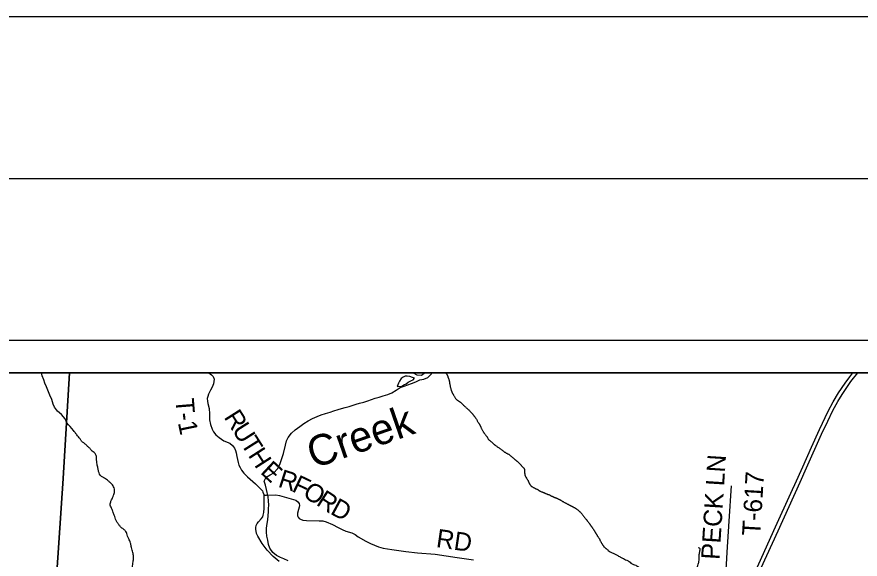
# Model space of a CAD drawing. Extents: x -13.7 to 34, y 0 to 32.3.
# Drawn here: x 25.84 to 28.447, y 20.324 to 22 of the extents above; entities that cross this region are included whole.
import ezdxf

# ---------------------------------------------------------------- set-up
doc = ezdxf.new("R2010")
doc.units = 0
for name, color, linetype in [('GM_X_Corporation', 7, 'Continuous'), ('GM_X_Major_River', 7, 'Continuous'), ('GM_X_Major_River_Text', 7, 'Continuous'), ('GM_X_Minor_River', 7, 'Continuous'), ('GM_X_State_Route', 7, 'Continuous'), ('GM_X_Township_Road', 7, 'Continuous'), ('GM_X_Township_Road_Text', 7, 'Continuous'), ('SH_Border', 7, 'Continuous'), ('SH_Cut_Line', 7, 'Continuous'), ('SH_Data', 7, 'Continuous')]:
    doc.layers.add(name, color=color, linetype=linetype)

msp = doc.modelspace()

# ---------------------------------------------------------------- linework, layer by layer
at = {"layer": 'GM_X_Corporation'}
for points in [[(25.8396, 18.3951), (25.8512, 18.5523), (25.8521, 18.5644), (25.8715, 18.8281), (25.8969, 19.1723), (25.8969, 19.2407), (25.917, 19.5276), (25.9325, 19.8164), (25.9462, 20.0191), (25.9566, 20.1753), (25.9834, 20.5724), (26.0026, 20.9), (23.5167, 20.9)], [(25.8396, 18.3951), (25.8512, 18.5523), (25.8521, 18.5644), (25.8715, 18.8281), (25.8969, 19.1723), (25.8969, 19.2407), (25.917, 19.5276), (25.9325, 19.8164), (25.9462, 20.0191), (25.9566, 20.1753), (25.9834, 20.5724), (26.0026, 20.9), (23.5167, 20.9)], [(29.9598, 20.9), (26.0026, 20.9), (25.9834, 20.5724), (25.9566, 20.1753), (25.9462, 20.0191), (25.9325, 19.8164), (25.917, 19.5276), (25.8969, 19.2407), (25.8969, 19.1723), (25.8715, 18.8281), (25.8521, 18.5644), (25.8512, 18.5523), (25.8396, 18.3951), (25.8286, 18.2247), (25.8036, 17.8534), (25.7648, 17.1991), (25.7595, 17.1252), (25.7591, 17.1039), (25.7561, 17.0683), (25.752, 17.037), (25.7481, 16.9763), (25.7164, 16.6052), (25.6857, 16.1459), (25.6733, 15.948)], [(29.9598, 20.9), (26.0026, 20.9), (25.9834, 20.5724), (25.9566, 20.1753), (25.9462, 20.0191), (25.9325, 19.8164), (25.917, 19.5276), (25.8969, 19.2407), (25.8969, 19.1723), (25.8715, 18.8281), (25.8521, 18.5644), (25.8512, 18.5523), (25.8396, 18.3951), (25.8286, 18.2247), (25.8036, 17.8534), (25.7648, 17.1991), (25.7595, 17.1252), (25.7591, 17.1039), (25.7561, 17.0683), (25.752, 17.037), (25.7481, 16.9763), (25.7164, 16.6052), (25.6857, 16.1459), (25.6733, 15.948)]]:
    msp.add_lwpolyline(points, dxfattribs=at)
at = {"layer": 'GM_X_Major_River'}
for points in [[(26.6785, 20.3183), (26.6649, 20.3243), (26.6554, 20.3285), (26.6429, 20.3353), (26.6312, 20.3443), (26.6224, 20.3576), (26.6179, 20.3693), (26.6159, 20.3822), (26.6129, 20.3943), (26.6117, 20.4072), (26.6121, 20.419), (26.6139, 20.4341), (26.6154, 20.4451), (26.6173, 20.4584), (26.6176, 20.4698), (26.6184, 20.4804), (26.6187, 20.4906), (26.6179, 20.5035), (26.6168, 20.5164), (26.6122, 20.5391), (26.6087, 20.552), (26.6049, 20.5645), (26.611, 20.5771), (26.6231, 20.5839), (26.6348, 20.5908), (26.6457, 20.6029), (26.6525, 20.6158), (26.6559, 20.6253), (26.66, 20.6382), (26.6638, 20.65), (26.6702, 20.6758), (26.6736, 20.6891), (26.6792, 20.7001), (26.6886, 20.7126), (26.7007, 20.7237), (26.7143, 20.7335), (26.7276, 20.7431), (26.7408, 20.7507), (26.7544, 20.7579), (26.7684, 20.7644), (26.7809, 20.7701), (26.7937, 20.774), (26.8081, 20.7782), (26.8195, 20.7824), (26.8331, 20.7866), (26.8433, 20.7893), (26.8547, 20.7927), (26.8668, 20.7954), (26.8766, 20.7981), (26.8887, 20.8027), (26.8997, 20.8053), (26.9122, 20.8092), (26.9246, 20.8126), (26.9367, 20.8168), (26.9481, 20.821), (26.9602, 20.8245), (26.9727, 20.8287), (26.9871, 20.8329), (26.9988, 20.8382), (27.0124, 20.8459), (27.0245, 20.8539), (27.037, 20.8588), (27.0491, 20.8623), (27.0604, 20.8661), (27.0733, 20.8714), (27.0858, 20.8775), (27.0979, 20.8798), (27.1107, 20.8848), (27.1213, 20.8962), (27.1228, 20.9)], [(27.0695, 20.8828), (27.0627, 20.8851), (27.0543, 20.8877), (27.0467, 20.8896), (27.0407, 20.8892), (27.0343, 20.8865), (27.0278, 20.8815), (27.0229, 20.8739), (27.0199, 20.8679), (27.0154, 20.8576)], [(27.0154, 20.8576), (27.0298, 20.8588), (27.0366, 20.8622), (27.0434, 20.866), (27.0498, 20.871), (27.0559, 20.8737), (27.0604, 20.8759), (27.0653, 20.8782), (27.0695, 20.8828)], [(27.1019, 20.9), (27.091, 20.8916), (27.0774, 20.8919), (27.066, 20.898), (27.0588, 20.9)]]:
    msp.add_lwpolyline(points, dxfattribs=at)
at = {"layer": 'GM_X_Minor_River'}
msp.add_lwpolyline([(25.9945, 20.7448), (25.9889, 20.7569), (25.9779, 20.7705), (25.9662, 20.7815), (25.9563, 20.7936), (25.9525, 20.8031), (25.9483, 20.8171), (25.9418, 20.8308), (25.9354, 20.8455), (25.9312, 20.8562), (25.927, 20.8679), (25.9232, 20.8781), (25.9187, 20.8906), (25.9159, 20.9)], dxfattribs=at)
msp.add_open_spline([(27.1659, 20.9), (27.166, 20.8999), (27.166, 20.8998), (27.1661, 20.8998), (27.1675, 20.8977), (27.1691, 20.8958), (27.1701, 20.8935), (27.171, 20.8913), (27.1717, 20.8889), (27.1725, 20.8866), (27.1734, 20.8841), (27.1744, 20.8815), (27.1753, 20.8789), (27.1761, 20.8766), (27.1768, 20.8741), (27.1773, 20.8716), (27.1778, 20.8694), (27.1778, 20.867), (27.1782, 20.8648), (27.179, 20.8607), (27.1799, 20.8566), (27.1809, 20.8525), (27.1815, 20.85), (27.182, 20.8474), (27.1829, 20.8449), (27.1837, 20.8424), (27.1848, 20.8402), (27.1861, 20.8379), (27.1871, 20.836), (27.1882, 20.8341), (27.1893, 20.8321), (27.191, 20.8291), (27.1926, 20.8262), (27.1943, 20.8232), (27.1958, 20.8206), (27.1977, 20.818), (27.2002, 20.8162), (27.2022, 20.8147), (27.2044, 20.8133), (27.2065, 20.8118), (27.2083, 20.8105), (27.2102, 20.8092), (27.212, 20.8078), (27.2144, 20.806), (27.2161, 20.8035), (27.2183, 20.8015), (27.2201, 20.7999), (27.222, 20.7984), (27.2238, 20.7968), (27.2265, 20.7943), (27.2292, 20.7918), (27.2319, 20.7893), (27.2339, 20.7875), (27.2358, 20.7856), (27.2378, 20.7838), (27.2402, 20.7815), (27.2425, 20.7791), (27.2448, 20.7767), (27.2466, 20.7748), (27.2483, 20.7729), (27.2499, 20.7708), (27.2515, 20.7688), (27.2531, 20.7667), (27.2546, 20.7646), (27.2562, 20.7623), (27.2579, 20.76), (27.2593, 20.7576), (27.2614, 20.7543), (27.2634, 20.7509), (27.2654, 20.7475), (27.2669, 20.7452), (27.2683, 20.7429), (27.2698, 20.7406), (27.2709, 20.7387), (27.272, 20.7367), (27.273, 20.7347), (27.2742, 20.7324), (27.275, 20.7298), (27.2762, 20.7274), (27.2777, 20.7244), (27.2794, 20.7214), (27.2812, 20.7185), (27.2826, 20.7163), (27.284, 20.7141), (27.2855, 20.7119), (27.2876, 20.709), (27.29, 20.7063), (27.2921, 20.7033), (27.2935, 20.7014), (27.2943, 20.6991), (27.2957, 20.6971), (27.2973, 20.6949), (27.2991, 20.6927), (27.3012, 20.6909), (27.3034, 20.6889), (27.3056, 20.6869), (27.3078, 20.685), (27.3099, 20.6831), (27.312, 20.6813), (27.3141, 20.6794), (27.3158, 20.6779), (27.3177, 20.6765), (27.3196, 20.6751), (27.3233, 20.6723), (27.327, 20.6697), (27.3307, 20.6671), (27.3334, 20.6653), (27.3363, 20.6637), (27.3389, 20.6619), (27.3417, 20.66), (27.344, 20.6575), (27.3467, 20.6556), (27.3491, 20.6538), (27.3516, 20.6523), (27.3541, 20.6508), (27.3566, 20.6492), (27.3596, 20.6485), (27.3619, 20.6467), (27.3642, 20.6449), (27.3664, 20.6431), (27.3686, 20.6412), (27.3712, 20.6389), (27.3738, 20.6367), (27.3763, 20.6344), (27.3783, 20.6327), (27.3803, 20.631), (27.3822, 20.6293), (27.3842, 20.6276), (27.3866, 20.6263), (27.3885, 20.6245), (27.391, 20.6223), (27.3932, 20.6199), (27.3955, 20.6175), (27.3975, 20.6154), (27.3994, 20.6133), (27.4014, 20.6112), (27.4032, 20.6093), (27.4048, 20.6074), (27.4065, 20.6053), (27.408, 20.6036), (27.4091, 20.6014), (27.4093, 20.5992), (27.4096, 20.5969), (27.4093, 20.5946), (27.4095, 20.5923), (27.4096, 20.5904), (27.4097, 20.5885), (27.4101, 20.5866), (27.4112, 20.5813), (27.4138, 20.5766), (27.4164, 20.572), (27.4177, 20.5696), (27.4194, 20.5674), (27.4207, 20.565), (27.4218, 20.563), (27.4225, 20.5608), (27.4236, 20.5588), (27.4247, 20.5566), (27.426, 20.5546), (27.4275, 20.5526), (27.4292, 20.5504), (27.4311, 20.5485), (27.4334, 20.5471), (27.4364, 20.5453), (27.4393, 20.5438), (27.4424, 20.5422), (27.4446, 20.5411), (27.4469, 20.5401), (27.4491, 20.539), (27.4513, 20.5378), (27.4532, 20.5361), (27.4554, 20.535), (27.4586, 20.5333), (27.4618, 20.5318), (27.4651, 20.5305), (27.467, 20.5297), (27.4689, 20.5291), (27.4708, 20.5284), (27.4732, 20.5274), (27.4755, 20.5261), (27.4779, 20.5251), (27.4803, 20.5241), (27.483, 20.5237), (27.4854, 20.5226), (27.4881, 20.5214), (27.4905, 20.5197), (27.4932, 20.5185), (27.4953, 20.5175), (27.4974, 20.5165), (27.4996, 20.5156), (27.5019, 20.5146), (27.5043, 20.5137), (27.5067, 20.5127), (27.5092, 20.5117), (27.5117, 20.5106), (27.5142, 20.5095), (27.5167, 20.5082), (27.5192, 20.5068), (27.5216, 20.5054), (27.5244, 20.5038), (27.527, 20.5021), (27.5298, 20.5006), (27.5325, 20.4991), (27.5353, 20.4976), (27.538, 20.4961), (27.5409, 20.4946), (27.5437, 20.4931), (27.5466, 20.4917), (27.5487, 20.4906), (27.5508, 20.4895), (27.5529, 20.4884), (27.5548, 20.4875), (27.5567, 20.4865), (27.5585, 20.4856), (27.561, 20.4843), (27.5633, 20.4829), (27.5656, 20.4815), (27.5675, 20.4804), (27.5694, 20.4793), (27.5712, 20.4779), (27.5737, 20.4761), (27.5759, 20.474), (27.5782, 20.472), (27.5802, 20.4702), (27.5823, 20.4685), (27.5841, 20.4665), (27.5876, 20.4626), (27.5903, 20.4581), (27.5936, 20.454), (27.5958, 20.4512), (27.5983, 20.4486), (27.6005, 20.4458), (27.6021, 20.4438), (27.6033, 20.4416), (27.6049, 20.4396), (27.6067, 20.4372), (27.6089, 20.435), (27.6107, 20.4326), (27.6121, 20.4307), (27.6133, 20.4286), (27.6147, 20.4267), (27.6161, 20.4248), (27.6177, 20.4229), (27.619, 20.4209), (27.6208, 20.4183), (27.6224, 20.4157), (27.6241, 20.4131), (27.6253, 20.4112), (27.6265, 20.4093), (27.6277, 20.4073), (27.629, 20.4052), (27.63, 20.4029), (27.6313, 20.4007), (27.6327, 20.3984), (27.6341, 20.3961), (27.6356, 20.3937), (27.6372, 20.3912), (27.6391, 20.3889), (27.6407, 20.3864), (27.6418, 20.3844), (27.6424, 20.3822), (27.6435, 20.3802), (27.645, 20.3775), (27.6466, 20.3748), (27.6482, 20.3721), (27.6495, 20.3698), (27.6507, 20.3676), (27.6521, 20.3655), (27.6537, 20.3631), (27.6558, 20.3611), (27.658, 20.3592), (27.6599, 20.3576), (27.662, 20.3561), (27.6639, 20.3544), (27.6662, 20.3523), (27.6686, 20.3502), (27.6709, 20.3481)], degree=3, dxfattribs=at)
for points in [[(26.1039, 20.5779), (26.0976, 20.5834), (26.0941, 20.5903), (26.0917, 20.5995), (26.0904, 20.6053), (26.0895, 20.6114), (26.0881, 20.6175), (26.0869, 20.6252), (26.0861, 20.6354), (26.0845, 20.6465), (26.0787, 20.6532), (26.0724, 20.6575), (26.0669, 20.6646), (26.0607, 20.6705), (26.0533, 20.6776), (26.0467, 20.6831), (26.0404, 20.6882), (26.0353, 20.6956), (26.0306, 20.7015), (26.0255, 20.7077), (26.02, 20.7151), (26.0153, 20.7214), (25.9945, 20.7448)], [(26.2658, 19.8603), (26.2679, 19.867), (26.2699, 19.8727), (26.2728, 19.8786), (26.2745, 19.885), (26.2766, 19.8907), (26.2779, 19.8967), (26.2797, 19.9039), (26.2823, 19.9121), (26.2833, 19.9197), (26.2843, 19.9265), (26.2844, 19.9322), (26.2844, 19.9409), (26.2835, 19.9508), (26.283, 19.9573), (26.2821, 19.9638), (26.2808, 19.9711), (26.2799, 19.9791), (26.2784, 19.9897), (26.2779, 19.9981), (26.2764, 20.021), (26.2755, 20.0282), (26.2745, 20.0343), (26.2732, 20.0408), (26.2701, 20.05), (26.2677, 20.057), (26.2646, 20.065), (26.2615, 20.0746), (26.2598, 20.0823), (26.2589, 20.0899), (26.2578, 20.1013), (26.257, 20.1105), (26.2564, 20.1173), (26.2551, 20.1238), (26.2516, 20.1319), (26.2458, 20.1409), (26.2397, 20.1506), (26.2353, 20.1564), (26.2329, 20.1637), (26.2316, 20.1695), (26.2299, 20.1752), (26.2278, 20.1817), (26.2246, 20.1883), (26.2203, 20.1964), (26.216, 20.2023), (26.2098, 20.2097), (26.2037, 20.2228), (26.2002, 20.2294), (26.1947, 20.236), (26.1915, 20.2433), (26.1902, 20.251), (26.1917, 20.2597), (26.1931, 20.2672), (26.1949, 20.2759), (26.1958, 20.2819), (26.1964, 20.2884), (26.1975, 20.2986), (26.1982, 20.3069), (26.1996, 20.3156), (26.2002, 20.3213), (26.2008, 20.3281), (26.2006, 20.335), (26.1993, 20.3411), (26.1976, 20.348), (26.1956, 20.3556), (26.1936, 20.3629), (26.1913, 20.3729), (26.1888, 20.3802), (26.186, 20.3863), (26.1821, 20.3941), (26.1797, 20.4025), (26.1769, 20.4091), (26.1695, 20.4161), (26.1607, 20.4233), (26.1548, 20.4307), (26.149, 20.4389), (26.1455, 20.4469), (26.1427, 20.4554), (26.1389, 20.4646), (26.1372, 20.4715), (26.1347, 20.4773), (26.1312, 20.4843), (26.1287, 20.4908), (26.1294, 20.498), (26.1327, 20.5066), (26.1359, 20.513), (26.1392, 20.5209), (26.1409, 20.5269), (26.1419, 20.5329), (26.1417, 20.5398), (26.139, 20.5475), (26.1357, 20.5533), (26.1302, 20.5588), (26.1232, 20.5651), (26.1173, 20.5702), (26.111, 20.5735), (26.1039, 20.5779)], [(27.6709, 20.3481), (27.678, 20.3445), (27.6877, 20.3396), (27.6959, 20.3355), (27.7045, 20.3307), (27.7123, 20.3266), (27.7179, 20.3238), (27.7254, 20.3201), (27.7329, 20.3161), (27.7384, 20.3113), (27.7462, 20.3073), (27.753, 20.3048), (27.7586, 20.3015), (27.7649, 20.2979), (27.7724, 20.2958), (27.7781, 20.2948), (27.7864, 20.293), (27.7928, 20.2913), (27.7992, 20.2892), (27.809, 20.2873), (27.8146, 20.2845), (27.8202, 20.2832), (27.8262, 20.2815), (27.8334, 20.2797), (27.8394, 20.2784), (27.8455, 20.2774), (27.8545, 20.2767), (27.8633, 20.276), (27.8788, 20.2755), (27.8857, 20.2761), (27.8933, 20.2769), (27.9001, 20.2779), (27.9074, 20.2795), (27.9143, 20.2816), (27.9201, 20.284), (27.9262, 20.2857), (27.9324, 20.2889), (27.9382, 20.2929), (27.9437, 20.2984), (27.945, 20.3041), (27.9475, 20.3109), (27.9485, 20.3165), (27.949, 20.3321), (27.9496, 20.3378), (27.9505, 20.3438), (27.9515, 20.3495), (27.9524, 20.3555), (27.9465, 20.3588)]]:
    msp.add_spline(points, degree=3, dxfattribs=at)
at = {"layer": 'GM_X_State_Route'}
for points in [[(28.1107, 20.2589), (28.1799, 20.4118), (28.2375, 20.5389), (28.2446, 20.5547), (28.2691, 20.6091), (28.2962, 20.67), (28.3208, 20.7243), (28.3479, 20.7813), (28.3636, 20.8102), (28.3799, 20.8373), (28.4002, 20.8679), (28.4151, 20.8875), (28.4245, 20.9)], [(28.1237, 20.2584), (28.1928, 20.4107), (28.2612, 20.5615), (28.2805, 20.6059), (28.3274, 20.7099), (28.3464, 20.7503), (28.3625, 20.7831), (28.3776, 20.811), (28.3912, 20.8328), (28.4179, 20.8724), (28.4395, 20.9)]]:
    msp.add_lwpolyline(points, dxfattribs=at)
at = {"layer": 'GM_X_Township_Road'}
for points in [[(26.433, 20.9), (26.4416, 20.8938), (26.4465, 20.8877), (26.4495, 20.8802), (26.449, 20.8732), (26.4476, 20.8659), (26.446, 20.8608), (26.4427, 20.8536), (26.4384, 20.8455), (26.4321, 20.8331), (26.4299, 20.8264), (26.4287, 20.8197), (26.4289, 20.8117), (26.4307, 20.805), (26.434, 20.7895), (26.4351, 20.7731), (26.4356, 20.7545), (26.439, 20.7395), (26.4437, 20.7256), (26.4483, 20.7171), (26.4552, 20.7082), (26.4654, 20.6991), (26.4803, 20.6894), (26.4979, 20.6816), (26.5071, 20.6749), (26.5133, 20.6664), (26.5161, 20.6592), (26.5179, 20.6519), (26.5202, 20.6413), (26.5241, 20.6224), (26.5262, 20.6143), (26.5299, 20.6065), (26.5341, 20.5991), (26.5416, 20.5898), (26.5525, 20.5779), (26.5774, 20.5566), (26.5885, 20.5461), (26.5966, 20.5378), (26.5995, 20.5343), (26.6009, 20.5302), (26.6046, 20.5218), (26.6119, 20.5215), (26.6401, 20.5221), (26.6516, 20.5203), (26.6812, 20.5119), (26.702, 20.506), (26.7088, 20.5011), (26.7122, 20.4955), (26.7134, 20.4895), (26.7132, 20.4844), (26.7108, 20.4768), (26.7074, 20.4657), (26.7079, 20.4579), (26.7096, 20.4531), (26.7125, 20.4497), (26.7164, 20.4469), (26.7244, 20.4442), (26.7357, 20.4432), (26.7745, 20.4425), (26.7861, 20.4422), (26.7966, 20.4391), (26.816, 20.4306), (26.833, 20.4215), (26.846, 20.4149), (26.8569, 20.4102), (26.8755, 20.4044), (26.8857, 20.3995), (26.895, 20.3921), (26.9187, 20.3793), (26.9337, 20.3723), (26.9451, 20.3667), (26.9578, 20.3618), (26.9723, 20.3578), (26.999, 20.3531), (27.0429, 20.3473), (27.0783, 20.3434), (27.1334, 20.3386), (27.2013, 20.3282), (27.2511, 20.3217)], [(28.0294, 20.2529), (28.0337, 20.3068), (28.0358, 20.3449), (28.0423, 20.4405), (28.049, 20.5506)], [(26.6512, 20.3159), (26.632, 20.3318), (26.6136, 20.3508), (26.5979, 20.3717), (26.5848, 20.395), (26.5811, 20.4026), (26.5795, 20.4096), (26.5785, 20.4156), (26.579, 20.4213), (26.58, 20.428), (26.583, 20.4333), (26.587, 20.4391), (26.5956, 20.4481), (26.6, 20.4543), (26.6016, 20.4594), (26.603, 20.4676), (26.6041, 20.4813), (26.6048, 20.496), (26.6046, 20.5094), (26.6046, 20.5218)]]:
    msp.add_lwpolyline(points, dxfattribs=at)
at = {"layer": 'SH_Border'}
msp.add_lwpolyline([(1.5, 21.5), (33.5, 21.5), (33.5, 0.5), (1.5, 0.5)], close=True, dxfattribs=at)
at = {"layer": 'SH_Cut_Line'}
msp.add_lwpolyline([(0, 0), (34, 0), (34, 22), (0, 22)], close=True, dxfattribs=at)
at = {"layer": 'SH_Data'}
for points in [[(23.4167, 21), (30.4167, 21), (30.4167, 14), (23.4167, 14)], [(23.5167, 20.9), (30.3167, 20.9), (30.3167, 14.1), (23.5167, 14.1)]]:
    msp.add_lwpolyline(points, close=True, dxfattribs=at)

# ---------------------------------------------------------------- texts
at = {"layer": 'GM_X_Major_River_Text'}
msp.add_text('Creek', height=0.0947, rotation=19.0988, dxfattribs=at).set_placement((26.7569, 20.6026))
at = {"layer": 'GM_X_Township_Road_Text'}
for s, height, rotation, p in [('T', 0.0568, 274.6248, (26.3303, 20.8186)), ('R', 0.0568, 302.319, (26.4786, 20.7626)), ('-', 0.0568, 276.9198, (26.334, 20.7738)), ('U', 0.0568, 302.3208, (26.5036, 20.7232)), ('1', 0.0568, 281.6376, (26.3376, 20.7456)), ('T', 0.0568, 302.3207, (26.5303, 20.6809)), ('H', 0.0568, 302.7166, (26.5532, 20.6447)), ('E', 0.0568, 317.0494, (26.5902, 20.5907)), ('PECK LN', 0.05682, 86.3714, (28.0116, 20.3206)), ('R', 0.0568, 342.3324, (26.6447, 20.548)), ('T-617', 0.05682, 86.6338, (28.1381, 20.3946)), ('F', 0.0568, 334.5123, (26.6873, 20.5346)), ('O', 0.0568, 328.0894, (26.7204, 20.5189)), ('R', 0.0568, 327.0439, (26.7626, 20.4927)), ('D', 0.0568, 331.5761, (26.806, 20.4648)), ('RD', 0.05682, 351.7984, (27.134, 20.3611))]:
    msp.add_text(s, height=height, rotation=rotation, dxfattribs=at).set_placement(p)

doc.saveas('drawing.dxf')
